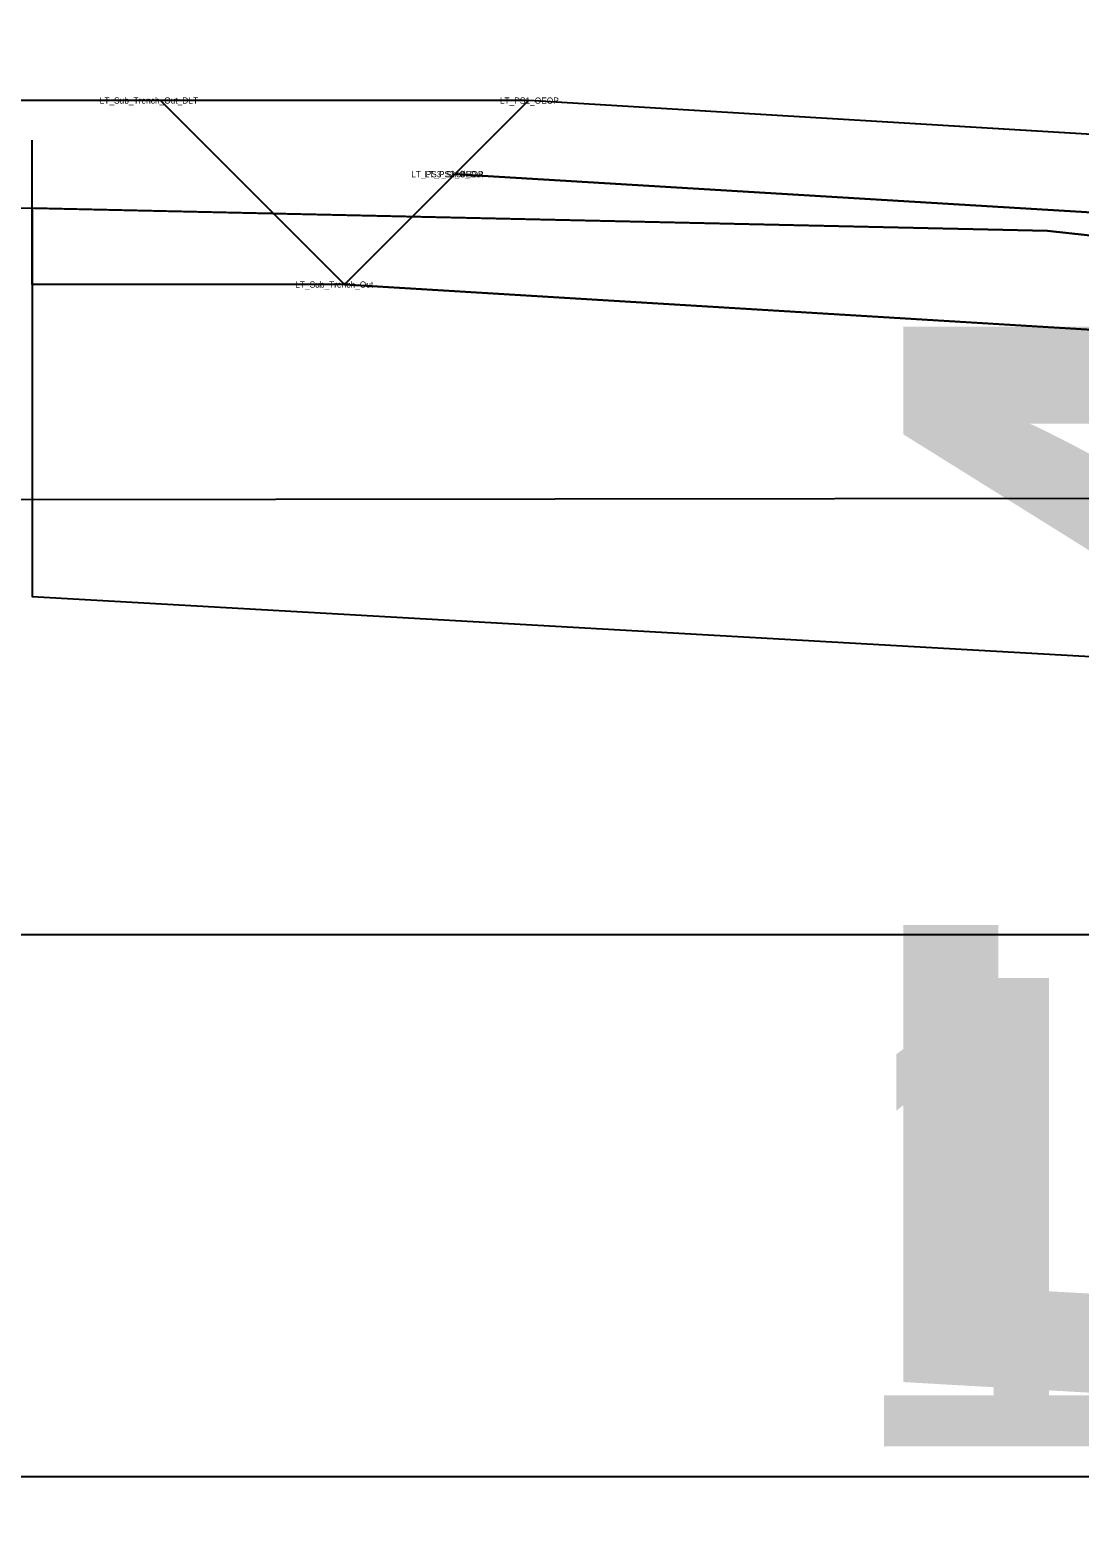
# Model space of a CAD drawing. Extents: x -516 to 303, y -10 to 5017.
# Drawn here: x 144.404 to 147.765, y 3999.803 to 4004.634 of the extents above; entities that cross this region are included whole.
import ezdxf

# ---------------------------------------------------------------- set-up
doc = ezdxf.new("R2010")
doc.units = 0
for name, color, linetype in [('Exist Cross Section Cell', 7, 'Continuous'), ('Exist XS Center Line Elevation Label', 7, 'Continuous'), ('Exist XS Ground Line', 7, 'Continuous'), ('Prop CMT Pvmt Surface Shoulder', 7, 'Continuous'), ('Prop CMT Shld Paved Course 1', 7, 'Continuous'), ('Prop CMT Shld Paved Course 2', 7, 'Continuous'), ('Prop CMT Shld Paved Course 3', 7, 'Continuous'), ('Prop CMT Slope Grass', 7, 'Continuous'), ('Prop CMT Subgrade Earthwork', 7, 'Continuous'), ('Prop Road Sect_ Material - Contact (General - Major)', 7, 'Continuous'), ('Prop Road Sect_ Material - Contact (General - Minor)', 7, 'Continuous'), ('Prop Road Sect_ Misc - Drafting Aid (solid line)', 7, 'Continuous'), ('Prop Road Sect_ Recs - UC Shallow (Outline)', 7, 'Continuous'), ('Prop Road Sect_ Recs - UC Shallow (Pattern)', 7, 'Continuous'), ('Scratch_Level_0', 7, 'Continuous')]:
    doc.layers.add(name, color=color, linetype=linetype)

msp = doc.modelspace()

# ---------------------------------------------------------------- linework, layer by layer
at = {"layer": 'Exist Cross Section Cell'}
msp.add_line((0, 4000), (150, 4000), dxfattribs=at)
at = {"layer": 'Exist XS Ground Line'}
msp.add_lwpolyline([(123.2543, 4004.5692), (133.1369, 4004.4101), (142.46, 4004.1074), (147.6616, 4003.9906), (148.1412, 4003.939), (148.4663, 4003.9205), (150, 4003.8465), (151.3908, 4003.7786), (154.3879, 4003.6043), (155.6241, 4003.5283), (157.4788, 4003.4176), (159.8437, 4003.281), (160.736, 4003.2336), (161.0589, 4003.2178), (161.7005, 4003.1807), (162.1024, 4003.1613), (173.2981, 4003.0432)], dxfattribs=at)
at = {"layer": 'Prop CMT Pvmt Surface Shoulder'}
msp.add_line((148, 4004.2875), (146, 4004.4083), dxfattribs=at)
at = {"layer": 'Prop CMT Shld Paved Course 1'}
for points in [[(148, 4004.2875), (146, 4004.4083), (145.7642, 4004.1725)], [(145.7642, 4004.1725), (148, 4004.0375)]]:
    msp.add_lwpolyline(points, dxfattribs=at)
at = {"layer": 'Prop CMT Shld Paved Course 2'}
for points in [[(148, 4004.0375), (145.7642, 4004.1725)], [(145.7642, 4004.1725), (145.7642, 4004.1725)], [(145.7642, 4004.1725), (148, 4004.0375)]]:
    msp.add_lwpolyline(points, dxfattribs=at)
at = {"layer": 'Prop CMT Shld Paved Course 3'}
for points in [[(145.7642, 4004.1725), (145.4106, 4003.8189)], [(148, 4004.0375), (145.7642, 4004.1725)], [(145.7642, 4004.1725), (145.7642, 4004.1725)], [(145.4106, 4003.8189), (148, 4003.6625)]]:
    msp.add_lwpolyline(points, dxfattribs=at)
at = {"layer": 'Prop CMT Slope Grass'}
msp.add_line((146, 4004.4083), (140, 4004.4107), dxfattribs=at)
at = {"layer": 'Prop CMT Subgrade Earthwork'}
for p, q in [((145.4106, 4003.8189), (144.8207, 4004.4087)), ((148, 4003.6625), (145.4106, 4003.8189))]:
    msp.add_line(p, q, dxfattribs=at)
at = {"layer": 'Prop Road Sect_ Material - Contact (General - Major)'}
msp.add_line((162.7643, 4003.1543), (77.3519, 4003.0357), dxfattribs=at)
at = {"layer": 'Prop Road Sect_ Material - Contact (General - Minor)'}
msp.add_line((115.0681, 4001.7367), (187.085, 4001.7367), dxfattribs=at)
at = {"layer": 'Prop Road Sect_ Misc - Drafting Aid (solid line)'}
for p, q in [((144.4106, 4003.8189), (144.4106, 4004.282)), ((145.4106, 4003.8189), (144.4106, 4003.8189)), ((144.4106, 4003.8189), (144.4106, 4002.8189))]:
    msp.add_line(p, q, dxfattribs=at)
at = {"layer": 'Prop Road Sect_ Recs - UC Shallow (Outline)'}
msp.add_lwpolyline([(160.5865, 4001.9022), (163.2517, 4001.7413), (164.2517, 4001.7413), (164.2517, 4003.1387), (162.7643, 4003.1543), (162.1024, 4003.1613), (161.7005, 4003.1807), (160.736, 4003.2336), (160.585, 4003.2416), (159.8437, 4003.281), (157.4788, 4003.4176), (155.6241, 4003.5283), (154.3879, 4003.6043), (150, 4003.8465), (148.4663, 4003.9205), (148.1412, 4003.939), (147.6616, 4003.9906), (144.4106, 4004.0636), (144.4106, 4002.8189)], close=True, dxfattribs=at)
at = {"layer": 'Prop Road Sect_ Recs - UC Shallow (Pattern)'}
msp.add_lwpolyline([(162.7643, 4003.1543), (162.1024, 4003.1613), (161.7005, 4003.1807), (160.736, 4003.2336), (160.585, 4003.2416), (159.8437, 4003.281), (157.4788, 4003.4176), (155.6241, 4003.5283), (154.3879, 4003.6043), (150, 4003.8465), (148.4663, 4003.9205), (148.1412, 4003.939), (147.6616, 4003.9906), (144.4106, 4004.0636), (144.4106, 4002.8189), (160.5865, 4001.9022), (163.2517, 4001.7413), (164.2517, 4001.7413), (164.2517, 4003.1387), (162.7643, 4003.1543)], dxfattribs=at)

# ---------------------------------------------------------------- texts
at = {"layer": 'Exist Cross Section Cell'}
msp.add_text('N 511544.9846', height=2.8, rotation=90, dxfattribs=at).set_placement((150, 3990))
at = {"layer": 'Exist XS Center Line Elevation Label'}
msp.add_text('160.85', height=1.5, dxfattribs=at).set_placement((146.985, 4000.0965))
at = {"layer": 'Scratch_Level_0'}
for s, p in [('LT_Sub_Trench_Out_DLT', (144.6264, 4004.3987)), ('LT_PS1_OEOP', (145.908, 4004.3983)), ('LT_PS3_Shelf_Out', (145.6241, 4004.1625)), ('LT_PS3_OEOP', (145.6666, 4004.1625)), ('LT_PS2_OEOP', (145.6666, 4004.1625)), ('LT_Sub_Trench_Out', (145.2526, 4003.8089))]:
    msp.add_text(s, height=0.02, dxfattribs=at).set_placement(p)

doc.saveas('drawing.dxf')
